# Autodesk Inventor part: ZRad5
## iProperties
Author: M. Sattler
Created: 2001-04
Part Number: ZRad5
Material: Standard
Document SubType Name: Modellieren
Designer: M. Sattler
Control State: 0
Master: False
Checked Out: False
PropertySet Name: Design Tracking Control
Shininess: 69.0
PropertySet Name: _Private Model Information
Density: 1.0
Volumn: 85.56280832693662
Area: 236.72886943575693
PropertySet Name: Model Information
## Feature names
1. Spirale1
2. Extrusion1
3. Runde Anordnung1 [Circular Pattern]
4. Extrusion2
5. Bohrung1 [Hole]
